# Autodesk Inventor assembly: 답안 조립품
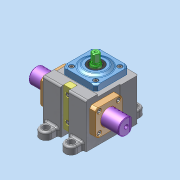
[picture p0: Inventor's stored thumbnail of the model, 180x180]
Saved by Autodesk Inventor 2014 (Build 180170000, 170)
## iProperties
Created: 2024-11
Part Number: 답안 조립품
Document SubType Name: Assembly
Designer: dg
Author: dg
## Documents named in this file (10)
- C:\Users\dg\Desktop\741104V1007\답안 조립품.iam
- C:\Users\dg\Desktop\741104V1007\본체.ipt
- C:\Users\dg\Documents\Inventor\피니언 축.ipt
- C:\Users\dg\Desktop\741104V1007\가져온 구성요소\깊음 홈 볼 베어링 6202\깊음 홈 볼 베어링 6202.ipt
- C:\Users\dg\Desktop\741104V1007\가져온 구성요소\커버\커버.ipt
- C:\Users\dg\Desktop\741104V1007\가져온 구성요소\오일 실 15 25 4\오일 실 15 25 4.ipt
- C:\Users\dg\Desktop\741104V1007\가져온 구성요소\수지 부시\수지 부시.ipt
- C:\Users\dg\Desktop\741104V1007\가져온 구성요소\래크\래크.ipt
- C:\Users\dg\Desktop\741104V1007\가져온 구성요소\스톱퍼\스톱퍼.ipt
- C:\Users\dg\Desktop\741104V1007\가져온 구성요소\육각 소켓 머리 볼트 M4x10\육각 소켓 머리 볼트 M4x10.ipt
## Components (1 placed, 1 different names)
1. 피니언 축:1
